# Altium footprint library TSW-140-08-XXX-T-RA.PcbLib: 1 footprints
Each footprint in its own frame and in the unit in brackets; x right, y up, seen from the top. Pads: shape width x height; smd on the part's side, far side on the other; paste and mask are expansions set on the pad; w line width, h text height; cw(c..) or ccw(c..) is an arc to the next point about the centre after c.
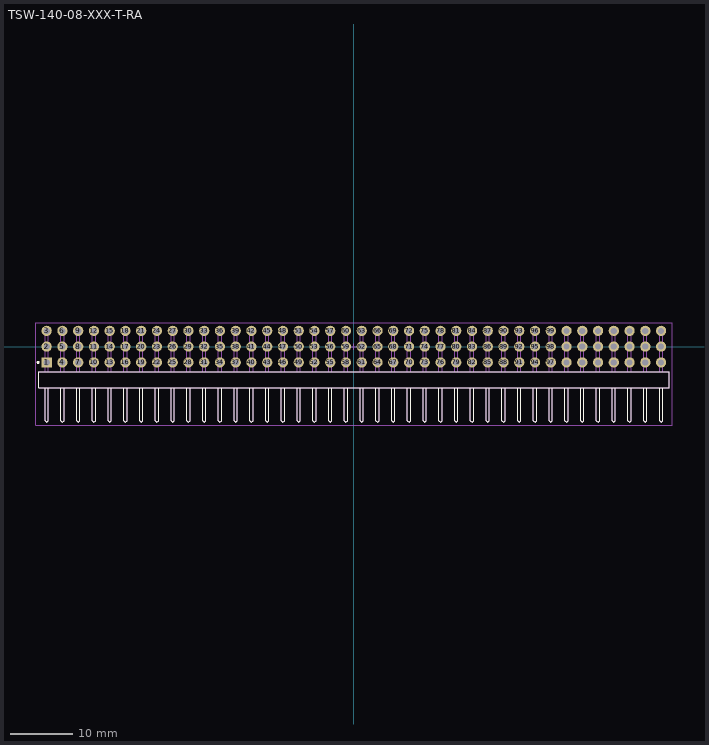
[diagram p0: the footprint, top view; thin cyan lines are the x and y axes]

## TSW-140-08-XXX-T-RA [mm] "2.54mm pitch, 40 pin, terminal strip; r/a, triple row"
height 8.1
pads (120):
  rect 1.65x1.65 hole 1 mask+0: 1(-49.53,-2.54)
  round 1.65 hole 1 mask+0: 2(-49.53,0) 3(-49.53,2.54) 4(-46.99,-2.54) 5(-46.99,0) 6(-46.99,2.54) 7(-44.45,-2.54) 8(-44.45,0) 9(-44.45,2.54) 10(-41.91,-2.54) 11(-41.91,0) 12(-41.91,2.54) 13(-39.37,-2.54) 14(-39.37,0) 15(-39.37,2.54) 16(-36.83,-2.54) 17(-36.83,0) 18(-36.83,2.54) 19(-34.29,-2.54) 20(-34.29,0) 21(-34.29,2.54) 22(-31.75,-2.54) 23(-31.75,0) 24(-31.75,2.54) 25(-29.21,-2.54) 26(-29.21,0) 27(-29.21,2.54) 28(-26.67,-2.54) 29(-26.67,0) 30(-26.67,2.54) 31(-24.13,-2.54) 32(-24.13,0) 33(-24.13,2.54) 34(-21.59,-2.54) 35(-21.59,0) 36(-21.59,2.54) 37(-19.05,-2.54) 38(-19.05,0) 39(-19.05,2.54) 40(-16.51,-2.54) 41(-16.51,0) 42(-16.51,2.54) 43(-13.97,-2.54) 44(-13.97,0) 45(-13.97,2.54) 46(-11.43,-2.54) 47(-11.43,0) 48(-11.43,2.54) 49(-8.89,-2.54) 50(-8.89,0) 51(-8.89,2.54) 52(-6.35,-2.54) 53(-6.35,0) 54(-6.35,2.54) 55(-3.81,-2.54) 56(-3.81,0) 57(-3.81,2.54) 58(-1.27,-2.54) 59(-1.27,0) 60(-1.27,2.54) 61(1.27,-2.54) 62(1.27,0) 63(1.27,2.54) 64(3.81,-2.54) 65(3.81,0) 66(3.81,2.54) 67(6.35,-2.54) 68(6.35,0) 69(6.35,2.54) 70(8.89,-2.54) 71(8.89,0) 72(8.89,2.54) 73(11.43,-2.54) 74(11.43,0) 75(11.43,2.54) 76(13.97,-2.54) 77(13.97,0) 78(13.97,2.54) 79(16.51,-2.54) 80(16.51,0) 81(16.51,2.54) 82(19.05,-2.54) 83(19.05,0) 84(19.05,2.54) 85(21.59,-2.54) 86(21.59,0) 87(21.59,2.54) 88(24.13,-2.54) 89(24.13,0) 90(24.13,2.54) 91(26.67,-2.54) 92(26.67,0) 93(26.67,2.54) 94(29.21,-2.54) 95(29.21,0) 96(29.21,2.54) 97(31.75,-2.54) 98(31.75,0) 99(31.75,2.54) 100(34.29,-2.54) 101(34.29,0) 102(34.29,2.54) 103(36.83,-2.54) 104(36.83,0) 105(36.83,2.54) 106(39.37,-2.54) 107(39.37,0) 108(39.37,2.54) 109(41.91,-2.54) 110(41.91,0) 111(41.91,2.54) 112(44.45,-2.54) 113(44.45,0) 114(44.45,2.54) 115(46.99,-2.54) 116(46.99,0) 117(46.99,2.54) 118(49.53,-2.54) 119(49.53,0) 120(49.53,2.54)
Top Overlay:
  drawing of 165 lines, arcs and shapes, not listed
Mechanical 12:
  drawing of 244 lines, arcs and shapes, not listed
Mechanical 13:
  drawing of 284 lines, arcs and shapes, not listed
  text ".Designator" at 0,0 h1.52
Mechanical 15:
  lines w0.05: -0.5,0 0.5,0 ; 0,-0.5 0,0.5 ; -51.28,-12.69 51.32,-12.69 51.32,3.86 -51.28,3.86 -51.28,-12.69
Mechanical 16:
  lines w0.001: -49.784,2.54 cw(c-49.53,2.54) -49.276,2.54 ; -47.244,2.54 cw(c-46.99,2.54) -46.736,2.54 ; -44.704,2.54 cw(c-44.45,2.54) -44.196,2.54 ; -42.164,2.54 cw(c-41.91,2.54) -41.656,2.54 ; -39.624,2.54 cw(c-39.37,2.54) -39.116,2.54 ; -37.084,2.54 cw(c-36.83,2.54) -36.576,2.54 ; -34.544,2.54 cw(c-34.29,2.54) -34.036,2.54 ; -32.004,2.54 cw(c-31.75,2.54) -31.496,2.54 ; -29.464,2.54 cw(c-29.21,2.54) -28.956,2.54 ; -26.924,2.54 cw(c-26.67,2.54) -26.416,2.54 ; -24.384,2.54 cw(c-24.13,2.54) -23.876,2.54 ; -21.844,2.54 cw(c-21.59,2.54) -21.336,2.54 ; -19.304,2.54 cw(c-19.05,2.54) -18.796,2.54 ; -16.764,2.54 cw(c-16.51,2.54) -16.256,2.54 ; -14.224,2.54 cw(c-13.97,2.54) -13.716,2.54 ; -11.684,2.54 cw(c-11.43,2.54) -11.176,2.54 ; -9.144,2.54 cw(c-8.89,2.54) -8.636,2.54 ; -6.604,2.54 cw(c-6.35,2.54) -6.096,2.54 ; -4.064,2.54 cw(c-3.81,2.54) -3.556,2.54 ; -1.524,2.54 cw(c-1.27,2.54) -1.016,2.54 ; 1.016,2.54 cw(c1.27,2.54) 1.524,2.54 ; 3.556,2.54 cw(c3.81,2.54) 4.064,2.54 ; 6.096,2.54 cw(c6.35,2.54) 6.604,2.54 ; 8.636,2.54 cw(c8.89,2.54) 9.144,2.54 ; 11.176,2.54 cw(c11.43,2.54) 11.684,2.54 ; 13.716,2.54 cw(c13.97,2.54) 14.224,2.54 ; 16.256,2.54 cw(c16.51,2.54) 16.764,2.54 ; 18.796,2.54 cw(c19.05,2.54) 19.304,2.54 ; 21.336,2.54 cw(c21.59,2.54) 21.844,2.54 ; 23.876,2.54 cw(c24.13,2.54) 24.384,2.54 ; 26.416,2.54 cw(c26.67,2.54) 26.924,2.54 ; 28.956,2.54 cw(c29.21,2.54) 29.464,2.54 ; 31.496,2.54 cw(c31.75,2.54) 32.004,2.54 ; 34.036,2.54 cw(c34.29,2.54) 34.544,2.54 ; 36.576,2.54 cw(c36.83,2.54) 37.084,2.54 ; 39.116,2.54 cw(c39.37,2.54) 39.624,2.54 ; 41.656,2.54 cw(c41.91,2.54) 42.164,2.54 ; 44.196,2.54 cw(c44.45,2.54) 44.704,2.54 ; 46.736,2.54 cw(c46.99,2.54) 47.244,2.54 ; 49.276,2.54 cw(c49.53,2.54) 49.784,2.54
